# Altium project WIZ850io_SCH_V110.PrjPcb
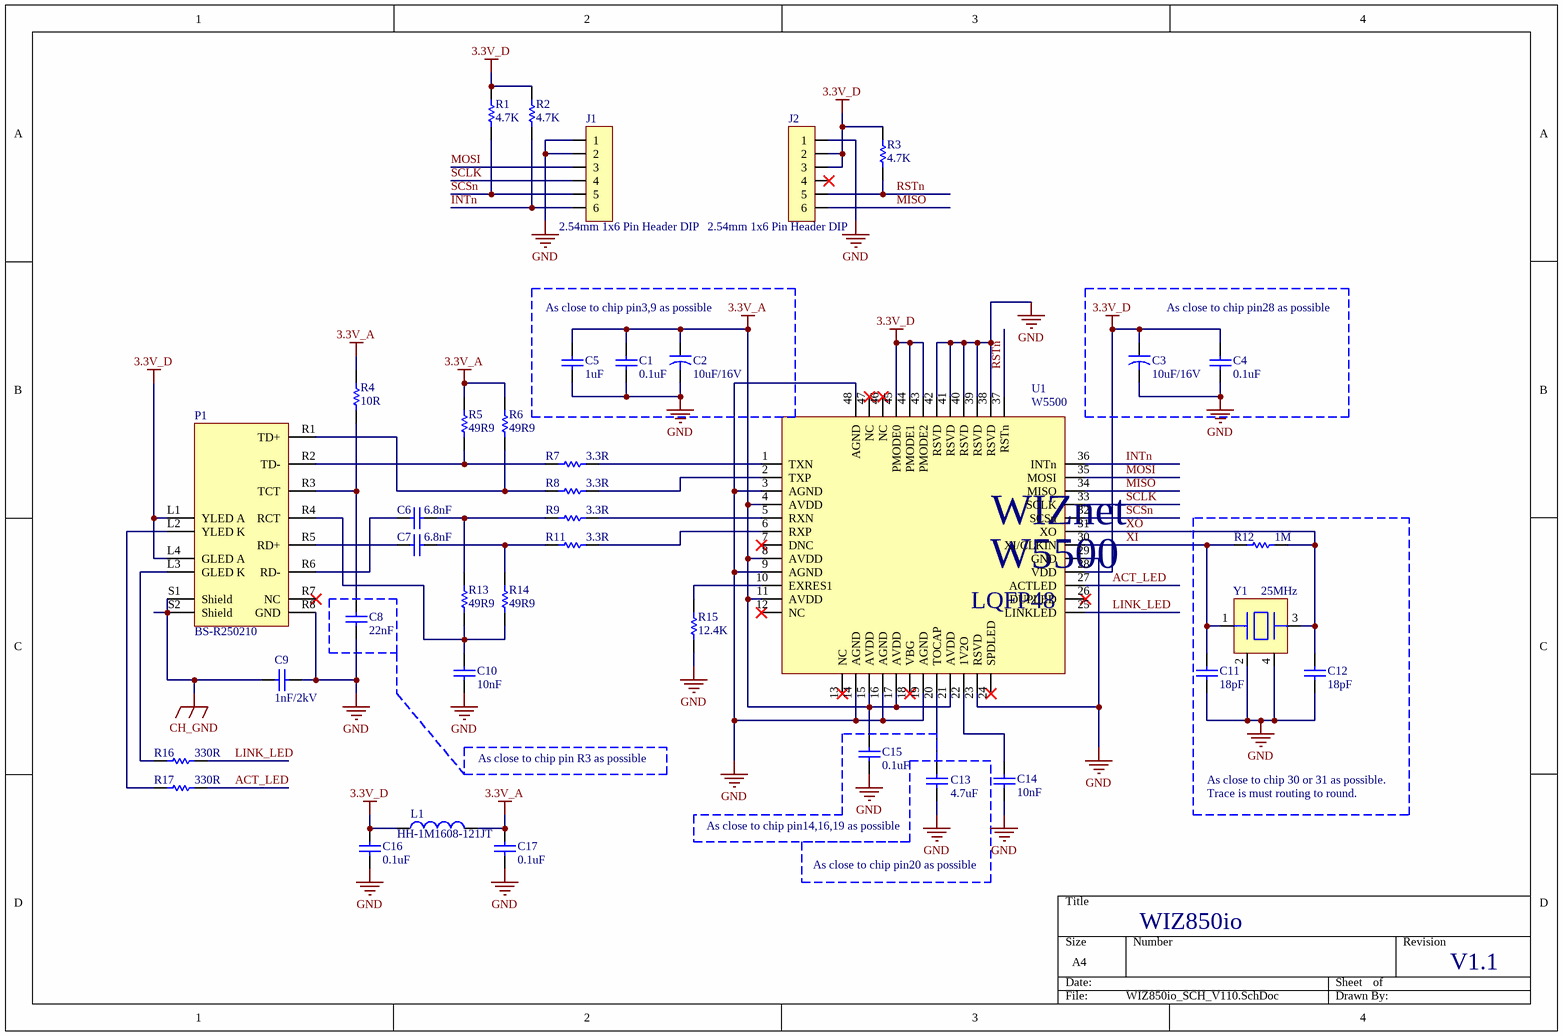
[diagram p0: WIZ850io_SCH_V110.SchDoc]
1 sheet, 39 parts. Net scope: global (net labels, ports and power ports of the same name join across sheets).
Board file: WIZ850io_SCH_V110.PcbDoc

## Sheet WIZ850io_SCH_V110.SchDoc
size A4; PageSetup: Record=PageOptions¦CenterHorizontal=True¦CenterVertical=True¦PrintScale=0.97¦XCorrection=1.00¦YCorrection=1.00¦PrintKind=1¦BorderSize=5000000¦LeftOffset=0¦BottomOffset=0¦Orientation=2¦PaperLength=1000¦PaperWidth=1000¦Scale=100¦PaperSource=7¦PrintQuality=-3¦MediaType=1¦DitherType=10¦PrintScaleMode=1¦PaperKind=A4¦PaperIndex=9

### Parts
C1  0.1uF  [CAP-0402]
C2  10uF/16V  [CAP-A Size]
C3  10uF/16V  [CAP-A Size]
C4  0.1uF  [CAP-0402]
C5  1uF  [CAP-0402]
C6  6.8nF  [CAP-0402]
C7  6.8nF  [CAP-0402]
C8  22nF  [CAP-0402]
C9  1nF/2kV  [CAP-1808]
C10  10nF  [CAP-0402]
C11  18pF  [CAP-0402]
C12  18pF  [CAP-0402]
C13  4.7uF  [CAP-0805]
C14  10nF  [CAP-0402]
C15  0.1uF  [CAP-0402]
C16  0.1uF  [CAP-0402]
C17  0.1uF  [CAP-0402]
J1  2.54mm 1x6 Pin Header DIP  [IDC-1X6]
J2  2.54mm 1x6 Pin Header DIP  [IDC-1X6]
L1  HH-1M1608-121JT  [IND-0603]
P1  BS-R250210  [BS-R250210]
R1  4.7K  [RES-0402]
R2  4.7K  [RES-0402]
R3  4.7K  [RES-0402]
R4  10R  [RES-0402]
R5  49R9  [RES-0402]
R6  49R9  [RES-0402]
R7  3.3R  [RES-0402]
R8  3.3R  [RES-0402]
R9  3.3R  [RES-0402]
R11  3.3R  [RES-0402]
R12  1M  [RES-0402]
R13  49R9  [RES-0402]
R14  49R9  [RES-0402]
R15  12.4K  [RES-0402]
R16  330R  [RES-0402]
R17  330R  [RES-0402]
U1  W5500  [WIZnet W5500]
Y1  25MHz  [OSC-82J0626]

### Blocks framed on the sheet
As close to chip pin3,9 as possible: C1 C2 C5
As close to chip pin28 as possible: C3 C4
As close to chip pin14,16,19 as possible: C15
As close to chip pin20 as possible: C13

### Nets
3.3V_A: C1.2 C2.1 C5.2 C15.2 C17.2 L1.2 R4.2 R5.2 R6.2 U1.4(AVDD) U1.8(AVDD) U1.11(AVDD) U1.15(AVDD) U1.17(AVDD) U1.21(AVDD)
3.3V_D: C3.1 C4.2 C16.2 J2.2 J2.3 L1.1 P1.L1(YLED_A) P1.L4(GLED_A) R1.2 R2.2 R3.2 U1.28(VDD) U1.43(PMODE2) U1.44(PMODE1) U1.45(PMODE0)
CH_GND: C9.2 P1.S1(Shield) P1.S2(Shield)
GND: C1.1 C2.2 C3.2 C4.1 C5.1 C8.1 C9.1 C10.1 C11.1 C12.1 C13.1 C14.1 C15.1 C16.1 C17.1 J1.1 J1.2 J2.1 P1.R8(GND) R15.1 U1.3(AGND) U1.9(AGND) U1.14(AGND) U1.16(AGND) U1.19(AGND) U1.23(RSVD) U1.29(GND) U1.38(RSVD) U1.39(RSVD) U1.40(RSVD) U1.41(RSVD) U1.42(RSVD) U1.48(AGND) Y1.2 Y1.4
ACT_LED: R17.2 U1.27(ACTLED)
INTn: J1.6 R2.1 U1.36(INTn)
LINK_LED: R16.2 U1.25(LINKLED)
MISO: J2.6 U1.34(MISO)
MOSI: J1.3 U1.35(MOSI)
RSTn: J2.5 R3.1 U1.37(RSTn)
SCLK: J1.4 U1.33(SCLK)
SCSn: J1.5 R1.1 U1.32(SCSn)
XI: C11.2 R12.1 U1.30(XI/CLKIN) Y1.1
XO: C12.2 R12.2 U1.31(XO) Y1.3
NetC6_1: C6.1 P1.R6(RD-)
NetC6_2: C6.2 R9.1 R13.2
NetC7_1: C7.1 P1.R5(RD+)
NetC7_2: C7.2 R11.1 R14.2
NetC8_2: C8.2 P1.R3(TCT) R4.1
NetC10_2: C10.2 P1.R4(RCT) R13.1 R14.1
NetC13_2: C13.2 U1.20(TOCAP)
NetC14_2: C14.2 U1.22(1V2O)
NetP1_L2: P1.L2(YLED_K) R17.1
NetP1_L3: P1.L3(GLED_K) R16.1
NetP1_R1: P1.R1(TD+) R6.1 R8.1
NetP1_R2: P1.R2(TD-) R5.1 R7.1
NetR7_2: R7.2 U1.1(TXN)
NetR8_2: R8.2 U1.2(TXP)
NetR9_2: R9.2 U1.5(RXN)
NetR11_2: R11.2 U1.6(RXP)
NetR15_2: R15.2 U1.10(EXRES1)

Not connected (* = marked no-connect by the designer): J2 4*; P1 R7(NC)*; U1 7(DNC)* 12(NC)* 13(NC)* 18(VBG)* 24(SPDLED)* 26(DUPLED)* 46(NC)* 47(NC)*

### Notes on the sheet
- As close to chip pin R3 as possible
- As close to chip 30 or 31 as possible.
- Trace is must routing to round.
- WIZ850io
- V1.1

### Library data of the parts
C1 C4-C8 C10-C13 C15-C17 = CAP-0402: Ceramic CAP 0402(1005)
C2 C3 = CAP-A Size: Tantla CAP A Size EIA/IECQ 3216
C9 = CAP-1808: Ceramic CAP 1808(4520)
C14 = CAP-0805: Ceramic CAP 0805(2012)
L1 = IND-0603: Inductor 0603(1608)
R1-R9 R11-R17 = RES-0402
U1 = W5500: WIZnet W5500
Y1 = OSC-82J0626-25MHz: X-tal 25MHz,3.2x2.5 SMD, CL=18pF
